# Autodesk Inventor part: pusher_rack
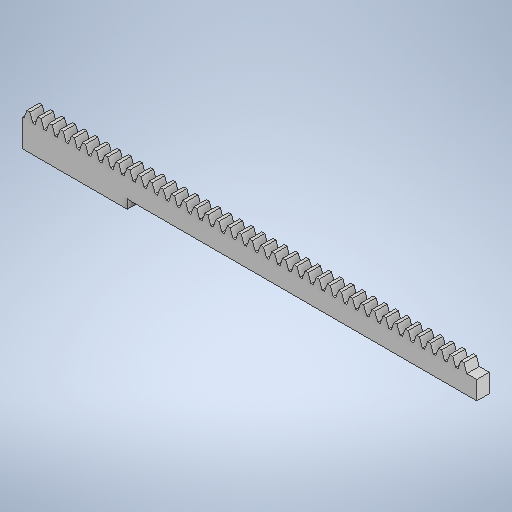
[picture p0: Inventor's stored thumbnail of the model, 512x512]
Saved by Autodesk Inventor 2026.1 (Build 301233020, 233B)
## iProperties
Company: meta-matic.com
Created: 2026-10
Part Number: pusher_rack
Material: Generic
Description: Rack Gear - meta-matic-generator 1.3
Document SubType Name: Modeling
Designer: alolo
Authority: META-MATIC-ID: 956ca585bc87
Density: 1 g/cm^3
Appearance: Default
Sending System: Open CASCADE
Preprocessor: meta-matic-generator 1.3
Title: Rack Gear_956ca585bc87
Author: Takahashi Mizuki @tkhsmz
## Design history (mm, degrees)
feature "Base1"
sketch "Sketch1"
  geometry: L1 (0, 10.5)-(0, 0) reference; L2 (10, 0)-(0, 0); L3 (0, 0)-(0, 10.5); L4 (0, 10.5)-(10, 10.5); L5 (10, 10.5)-(10, 0); 1 further point
  constraints: 8 end point, 2 parallel, 1 horizontal, 1 perpendicular
extrude "Extrusion1" join sketch "Sketch1" distance "d0" = 5; taper "d1" = 0 deg
sketch "Sketch3"
  geometry: L1 (0, 0)-(0, 10.5) reference; L2 (0, 0)-(256.327, 0) reference; L3 (256.327, 10.5)-(256.327, 0) reference; L4 (250.667, 10.5)-(256.327, 10.5) reference; L5 (249.029, 15)-(250.667, 10.5) reference; L6 (247.343, 15)-(249.029, 15) reference; L7 (245.705, 10.5)-(247.343, 15) reference; L8 (244.383, 10.5)-(245.705, 10.5) reference; L9 (242.745, 15)-(244.383, 10.5) reference; L10 (241.06, 15)-(242.745, 15) reference; L11 (239.422, 10.5)-(241.06, 15) reference; L12 (238.1, 10.5)-(239.422, 10.5) reference; L13 (236.462, 15)-(238.1, 10.5) reference; L14 (234.777, 15)-(236.462, 15) reference; L15 (233.139, 10.5)-(234.777, 15) reference; L16 (231.817, 10.5)-(233.139, 10.5) reference; L17 (230.179, 15)-(231.817, 10.5) reference; L18 (228.493, 15)-(230.179, 15) reference; L19 (226.856, 10.5)-(228.493, 15) reference; L20 (225.534, 10.5)-(226.856, 10.5) reference; L21 (223.896, 15)-(225.534, 10.5) reference; L22 (222.21, 15)-(223.896, 15) reference; L23 (220.572, 10.5)-(222.21, 15) reference; L24 (219.251, 10.5)-(220.572, 10.5) reference; L25 (217.613, 15)-(219.251, 10.5) reference; L26 (215.927, 15)-(217.613, 15) reference; L27 (214.289, 10.5)-(215.927, 15) reference; L28 (212.967, 10.5)-(214.289, 10.5) reference; L29 (211.33, 15)-(212.967, 10.5) reference; L30 (209.644, 15)-(211.33, 15) reference; L31 (208.006, 10.5)-(209.644, 15) reference; L32 (206.684, 10.5)-(208.006, 10.5) reference; L33 (205.046, 15)-(206.684, 10.5) reference; L34 (203.361, 15)-(205.046, 15) reference; L35 (201.723, 10.5)-(203.361, 15) reference; L36 (200.401, 10.5)-(201.723, 10.5) reference; L37 (198.763, 15)-(200.401, 10.5) reference; L38 (197.077, 15)-(198.763, 15) reference; L39 (195.44, 10.5)-(197.077, 15) reference; L40 (194.118, 10.5)-(195.44, 10.5) reference; L41 (192.48, 15)-(194.118, 10.5) reference; L42 (190.794, 15)-(192.48, 15) reference; L43 (189.156, 10.5)-(190.794, 15) reference; L44 (187.835, 10.5)-(189.156, 10.5) reference; L45 (186.197, 15)-(187.835, 10.5) reference; L46 (184.511, 15)-(186.197, 15) reference; L47 (182.873, 10.5)-(184.511, 15) reference; L48 (181.552, 10.5)-(182.873, 10.5) reference; L49 (179.914, 15)-(181.552, 10.5) reference; L50 (178.228, 15)-(179.914, 15) reference; L51 (176.59, 10.5)-(178.228, 15) reference; L52 (175.268, 10.5)-(176.59, 10.5) reference; L53 (173.63, 15)-(175.268, 10.5) reference; L54 (171.945, 15)-(173.63, 15) reference; L55 (170.307, 10.5)-(171.945, 15) reference; L56 (168.985, 10.5)-(170.307, 10.5) reference; L57 (167.347, 15)-(168.985, 10.5) reference; L58 (165.662, 15)-(167.347, 15) reference; L59 (164.024, 10.5)-(165.662, 15) reference; L60 (162.702, 10.5)-(164.024, 10.5) reference; L61 (161.064, 15)-(162.702, 10.5) reference; L62 (159.378, 15)-(161.064, 15) reference; L63 (157.741, 10.5)-(159.378, 15) reference; L64 (156.419, 10.5)-(157.741, 10.5) reference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; 1 further point
extrude "Extrusion2" cut sketch "Sketch3" distance "d2" = 3; taper "d3" = 0 deg
sketch "Sketch4"
  geometry: L1 (0, 0)-(0, 10.5) reference; L2 (0, 0)-(256.327, 0); L3 (256.327, 0)-(256.327, -5); L4 (256.327, -5)-(0, -5); L5 (0, -5)-(0, 0); L6 (256.327, 10.5)-(256.327, 0) reference; L7 (58.983, -5)-(58.983, 0); 1 further point
  constraints: 10 end point, 2 parallel, 2 perpendicular, 2 point on line, 1 collinear, 1 horizontal
  dimensions: "d4" = 5 distance of L2.end L3.end
extrude "Extrusion3" join sketch "Sketch4" stored distance "d5" = 5; taper "d6" = 0 deg
body "Solid1"
node "Projected Loop1"
